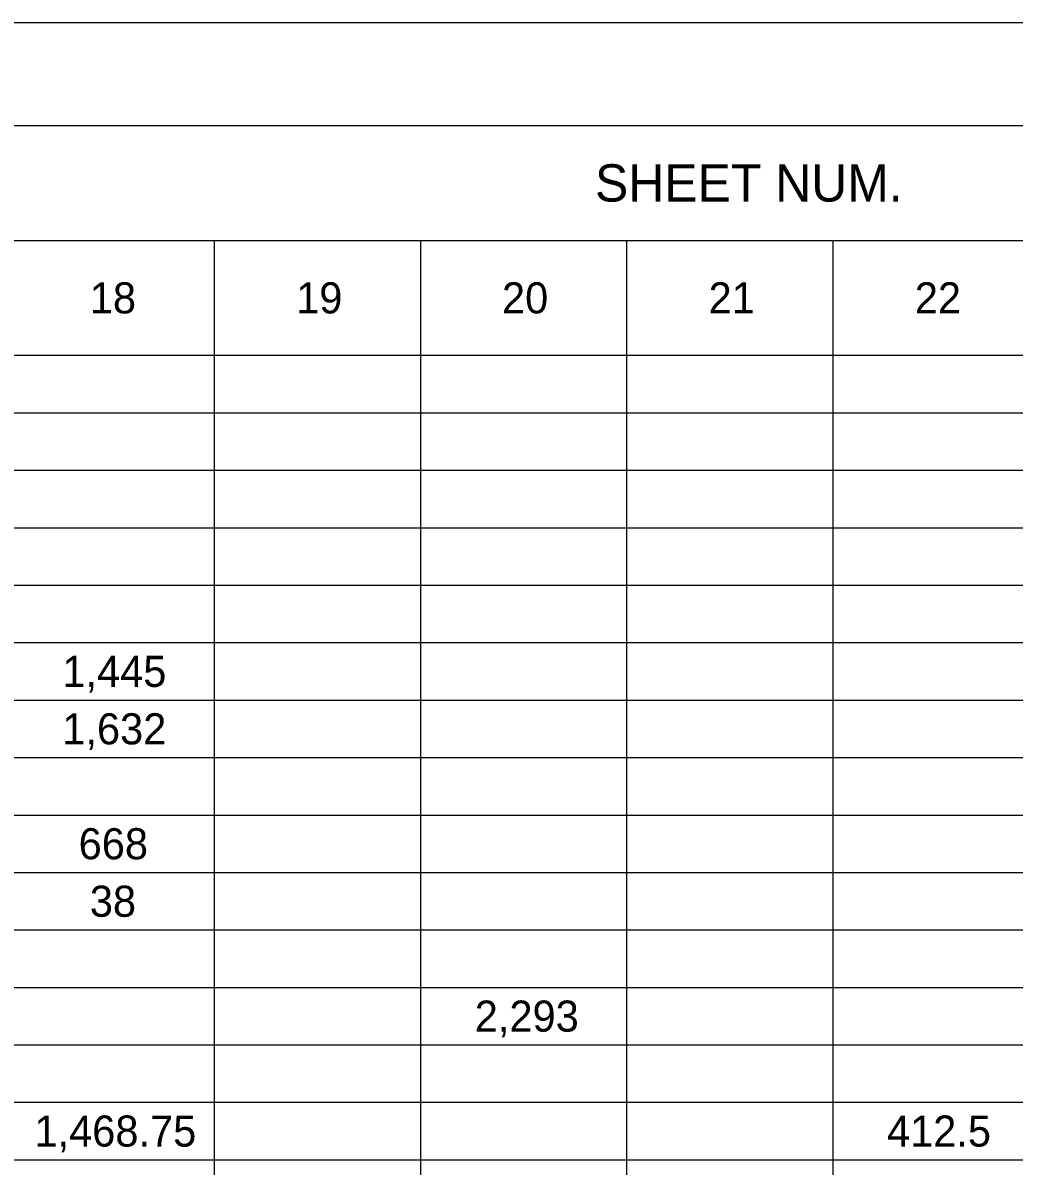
# Model space of a CAD drawing. Extents: x -31.7 to 37.3, y 0 to 22.
# Drawn here: x 4.59 to 9.42, y 16.43 to 22 of the extents above; entities that cross this region are included whole.
import ezdxf

# ---------------------------------------------------------------- set-up
doc = ezdxf.new("R2010")
doc.units = 0
for name, color, linetype in [('SH_Border', 7, 'Continuous'), ('SH_Cut_Line', 7, 'Continuous'), ('SH_Data', 7, 'Continuous'), ('SH_Text', 7, 'Continuous')]:
    doc.layers.add(name, color=color, linetype=linetype)

msp = doc.modelspace()

# ---------------------------------------------------------------- linework, layer by layer
at = {"layer": 'SH_Border'}
msp.add_lwpolyline([(1.5, 21.5), (33.5, 21.5), (33.5, 0.5), (1.5, 0.5)], close=True, dxfattribs=at)
at = {"layer": 'SH_Cut_Line'}
msp.add_lwpolyline([(0, 0), (34, 0), (34, 22), (0, 22)], close=True, dxfattribs=at)
at = {"layer": 'SH_Data'}
for p, q in [((1.5, 21.5), (32.0011, 21.5)), ((1.5, 20.94), (15.5648, 20.94)), ((5.5185, 20.94), (5.5185, 0.5016)), ((6.5231, 20.94), (6.5231, 0.5016)), ((7.5278, 20.94), (7.5278, 0.5016)), ((8.5324, 20.94), (8.5324, 0.5016)), ((1.5, 20.3801), (32.0011, 20.3801)), ((1.5, 20.1001), (32.0011, 20.1001)), ((1.5, 19.8201), (32.0011, 19.8201)), ((1.5, 19.5402), (32.0011, 19.5402)), ((1.5, 19.2602), (32.0011, 19.2602)), ((1.5, 18.9802), (32.0011, 18.9802)), ((1.5, 18.7002), (32.0011, 18.7002)), ((1.5, 18.4202), (32.0011, 18.4202)), ((1.5, 18.1403), (32.0011, 18.1403)), ((1.5, 17.8603), (32.0011, 17.8603)), ((1.5, 17.5803), (32.0011, 17.5803)), ((1.5, 17.3003), (32.0011, 17.3003)), ((1.5, 17.0204), (32.0011, 17.0204)), ((1.5, 16.7404), (32.0011, 16.7404)), ((1.5, 16.4604), (32.0011, 16.4604))]:
    msp.add_line(p, q, dxfattribs=at)

# ---------------------------------------------------------------- texts
at = {"layer": 'SH_Text'}
for s, height, p in [('SHEET NUM.', 0.18182, (7.3735, 21.1291)), ('18', 0.15152, (4.9118, 20.5843)), ('19', 0.15152, (5.9174, 20.5843)), ('20', 0.15152, (6.9203, 20.5843)), ('21', 0.15152, (7.9271, 20.5843)), ('22', 0.15152, (8.9318, 20.5843)), ('1,445', 0.15152, (4.778, 18.7645)), ('1,632', 0.15152, (4.7777, 18.4845)), ('668', 0.15152, (4.8574, 17.9245)), ('38', 0.15152, (4.9118, 17.6445)), ('2,293', 0.15152, (6.7875, 17.0846)), ('1,468.75', 0.15152, (4.642, 16.5246)), ('412.5', 0.15152, (8.7962, 16.5246))]:
    msp.add_text(s, height=height, dxfattribs=at).set_placement(p)

doc.saveas('drawing.dxf')
